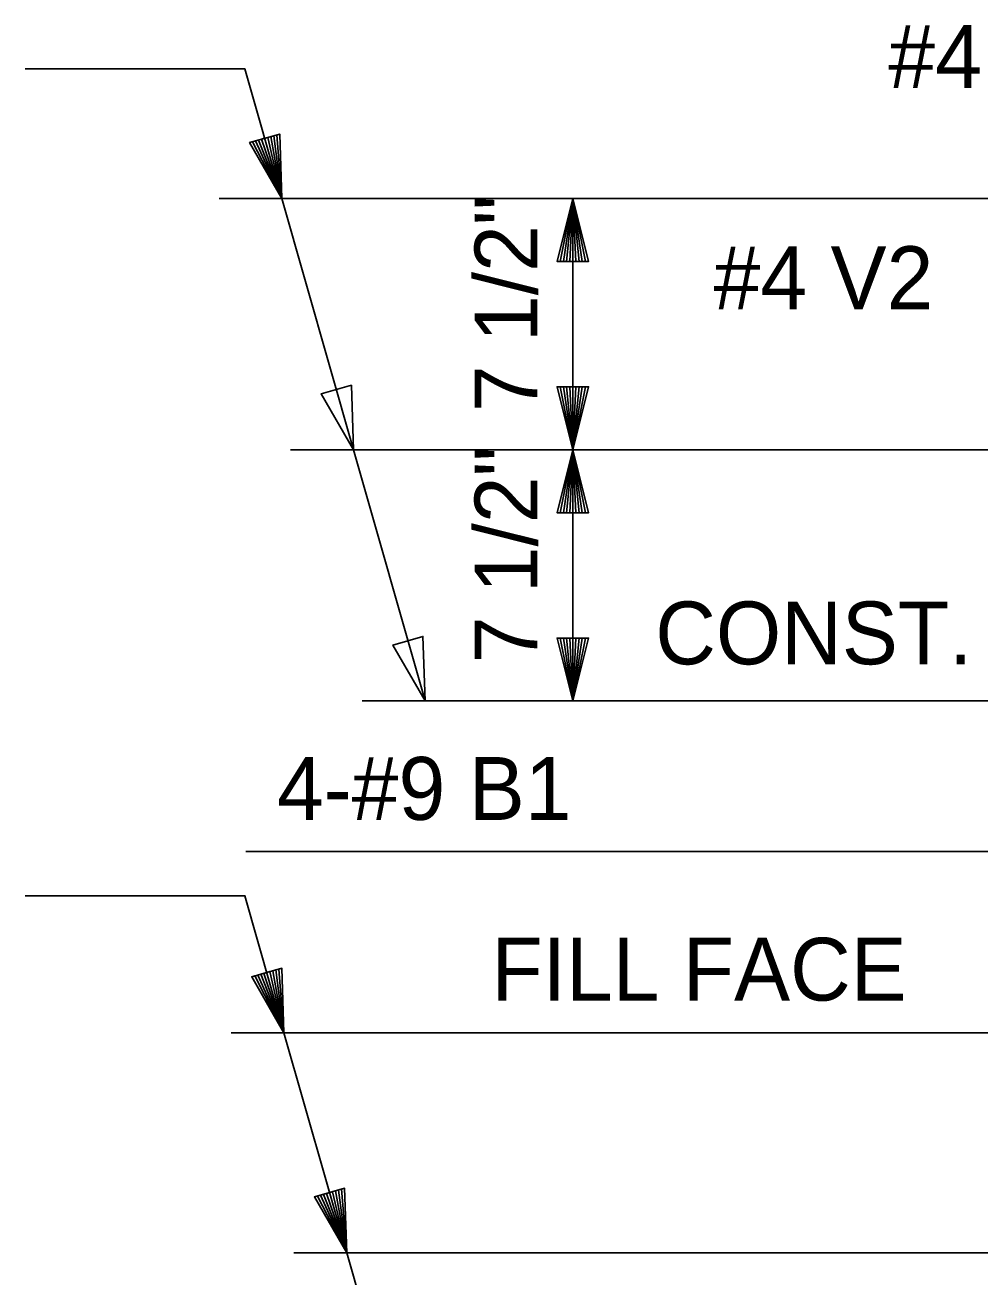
# Model space of a CAD drawing. Extents: x -41 to 251, y -169 to 237.
# Drawn here: x 40.67 to 45.01, y -153.21 to -147.52 of the extents above; entities that cross this region are included whole.
import ezdxf

# ---------------------------------------------------------------- set-up
doc = ezdxf.new("R2010")
doc.units = 0
for name, color, linetype in [('Arrowhead Terminators CELL', 7, 'Continuous'), ('Dimension Lines CELL', 7, 'Continuous'), ('Text', 7, 'Continuous'), ('Text CELL', 7, 'Continuous')]:
    doc.layers.add(name, color=color, linetype=linetype)

msp = doc.modelspace()

# ---------------------------------------------------------------- linework, layer by layer
at = {"layer": 'Arrowhead Terminators CELL'}
for points in [[(41.7636, -148.0311), (41.7499, -148.035), (41.8417, -148.3048), (41.7363, -148.039), (41.7226, -148.0429), (41.8417, -148.3048), (41.7089, -148.0466), (41.6951, -148.0505), (41.8417, -148.3048), (41.832, -148.0116), (41.8184, -148.0154), (41.8417, -148.3048), (41.8047, -148.0193), (41.7911, -148.0233), (41.8417, -148.3048), (41.7773, -148.0272), (41.6951, -148.0505), (41.832, -148.0116), (41.8417, -148.3048), (41.6951, -148.0505)], [(43.1642, -148.5908), (43.1499, -148.5908), (43.1642, -148.3048), (43.1356, -148.5908), (43.1213, -148.5908), (43.1642, -148.3048), (43.1069, -148.5908), (43.0927, -148.5908), (43.1642, -148.3048), (43.2357, -148.5908), (43.2214, -148.5908), (43.1642, -148.3048), (43.2071, -148.5908), (43.1928, -148.5908), (43.1642, -148.3048), (43.1785, -148.5908), (43.0927, -148.5908), (43.2357, -148.5908), (43.1642, -148.3048), (43.0927, -148.5908)], [(43.1642, -149.1603), (43.1785, -149.1603), (43.1642, -149.4463), (43.1928, -149.1603), (43.2071, -149.1603), (43.1642, -149.4463), (43.2214, -149.1603), (43.2357, -149.1603), (43.1642, -149.4463), (43.0927, -149.1603), (43.1069, -149.1603), (43.1642, -149.4463), (43.1213, -149.1603), (43.1356, -149.1603), (43.1642, -149.4463), (43.1499, -149.1603), (43.2357, -149.1603), (43.0927, -149.1603), (43.1642, -149.4463), (43.2357, -149.1603)], [(43.1642, -149.7323), (43.1499, -149.7323), (43.1642, -149.4463), (43.1356, -149.7323), (43.1213, -149.7323), (43.1642, -149.4463), (43.1069, -149.7323), (43.0927, -149.7323), (43.1642, -149.4463), (43.2357, -149.7323), (43.2214, -149.7323), (43.1642, -149.4463), (43.2071, -149.7323), (43.1928, -149.7323), (43.1642, -149.4463), (43.1785, -149.7323), (43.0927, -149.7323), (43.2357, -149.7323), (43.1642, -149.4463), (43.0927, -149.7323)], [(43.1642, -150.3019), (43.1785, -150.3019), (43.1642, -150.5879), (43.1928, -150.3019), (43.2071, -150.3019), (43.1642, -150.5879), (43.2214, -150.3019), (43.2357, -150.3019), (43.1642, -150.5879), (43.0927, -150.3019), (43.1069, -150.3019), (43.1642, -150.5879), (43.1213, -150.3019), (43.1356, -150.3019), (43.1642, -150.5879), (43.1499, -150.3019), (43.2357, -150.3019), (43.0927, -150.3019), (43.1642, -150.5879), (43.2357, -150.3019)], [(41.7733, -151.8218), (41.7597, -151.8257), (41.8514, -152.0955), (41.746, -151.8296), (41.7323, -151.8336), (41.8514, -152.0955), (41.7187, -151.8373), (41.7048, -151.8412), (41.8514, -152.0955), (41.8417, -151.8023), (41.8282, -151.8061), (41.8514, -152.0955), (41.8144, -151.81), (41.8008, -151.8139), (41.8514, -152.0955), (41.7871, -151.8179), (41.7048, -151.8412), (41.8417, -151.8023), (41.8514, -152.0955), (41.7048, -151.8412)], [(42.0585, -152.822), (42.0449, -152.8259), (42.1366, -153.0957), (42.0312, -152.8298), (42.0175, -152.8337), (42.1366, -153.0957), (42.0038, -152.8375), (41.99, -152.8414), (42.1366, -153.0957), (42.1269, -152.8024), (42.1133, -152.8063), (42.1366, -153.0957), (42.0996, -152.8102), (42.086, -152.8141), (42.1366, -153.0957), (42.0722, -152.818), (41.99, -152.8414), (42.1269, -152.8024), (42.1366, -153.0957), (41.99, -152.8414)]]:
    msp.add_lwpolyline(points, dxfattribs=at)
for points in [[(42.1672, -149.4463), (42.1576, -149.1531), (42.0207, -149.1921)], [(42.4927, -150.5879), (42.483, -150.2946), (42.3462, -150.3336)]]:
    msp.add_lwpolyline(points, close=True, dxfattribs=at)
at = {"layer": 'Dimension Lines CELL'}
for p, q in [((46.7518, -148.3048), (41.5563, -148.3048)), ((43.1642, -148.3048), (43.1642, -149.4463)), ((47.7592, -149.4463), (41.8818, -149.4463)), ((43.1642, -149.4463), (43.1642, -150.5879)), ((46.7518, -150.5879), (42.2073, -150.5879)), ((50.793, -151.2721), (41.6784, -151.2721)), ((46.7672, -152.0955), (41.6116, -152.0955)), ((46.7672, -153.0957), (41.8965, -153.0957))]:
    msp.add_line(p, q, dxfattribs=at)
for points in [[(41.8417, -148.3048), (41.6739, -147.7161), (40.6745, -147.7161)], [(42.1672, -149.4463), (41.8417, -148.3048)], [(42.4927, -150.5879), (42.1672, -149.4463)], [(41.8514, -152.0955), (41.6739, -151.4727), (40.6745, -151.4727)], [(42.1366, -153.0957), (41.8514, -152.0955)], [(42.4218, -154.0958), (42.1366, -153.0957)]]:
    msp.add_lwpolyline(points, dxfattribs=at)

# ---------------------------------------------------------------- texts
at = {"layer": 'Text'}
msp.add_text('FILL FACE', height=0.28539, dxfattribs=at).set_placement((42.7944, -151.9494))
at = {"layer": 'Text CELL'}
for s, height, p in [('#4 U1', 0.28588, (44.5987, -147.8022)), ('#4 V2', 0.28588, (43.804, -148.8076)), ('CONST. JT.', 0.28539, (43.539, -150.4214)), ('4-#9 B1', 0.28588, (41.8195, -151.1284))]:
    msp.add_text(s, height=height, dxfattribs=at).set_placement(p)
for p in [(43.0032, -149.2748), (43.0032, -150.4164)]:
    msp.add_text('7 1/2"', height=0.28539, rotation=90, dxfattribs=at).set_placement(p)

doc.saveas('drawing.dxf')
